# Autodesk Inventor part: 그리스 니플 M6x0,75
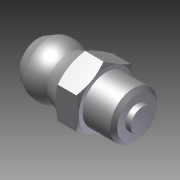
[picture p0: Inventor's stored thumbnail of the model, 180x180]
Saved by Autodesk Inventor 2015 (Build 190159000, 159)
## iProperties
Created: 2026-04
Part Number: 그리스 니플 M6x0,75
Material: 일반
Document SubType Name: Modeling
Designer: User
Density: 1 g/cm^3
Appearance: 기본값
Author: User
Author: jhkim
Description: 윤활 니플, 원추 유형 A
Creation Date: 2026-03-26
Sending System: Autodesk Inventor 2026
Preprocessor: ST-DEVELOPER v20.1
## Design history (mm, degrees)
node "그리스 니플 M6x0,751"
body "Solid1"
node "기준1"
